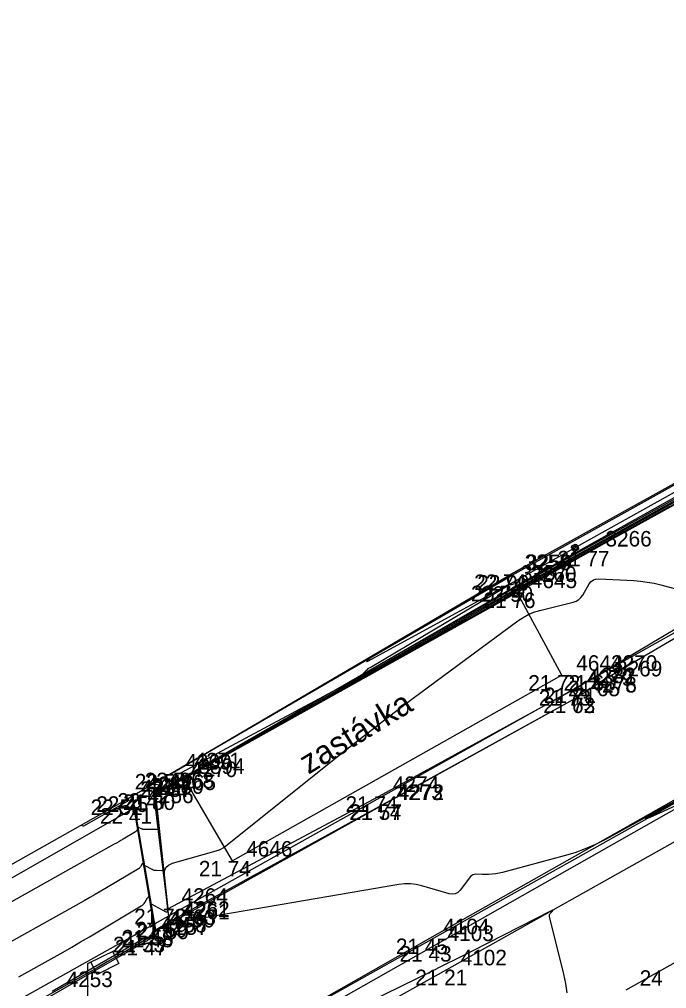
# Model space of a CAD drawing. Extents: x -702257 to -701487, y -1009871 to -1008841.
# Drawn here: x -701987.85 to -701977.44, y -1009621.47 to -1009605.88 of the extents above; entities that cross this region are included whole.
import ezdxf

# ---------------------------------------------------------------- set-up
doc = ezdxf.new("R2010")
doc.units = 0
for name, color, linetype in [('Ex_Major Contours', 7, 'Continuous'), ('Ex_Minor Contours', 7, 'Continuous'), ('Z_betonova_konstrukce', 7, 'Continuous'), ('Z_body', 7, 'Continuous'), ('Z_body_cisla', 7, 'Continuous'), ('Z_body_vysky_redukovane', 7, 'Continuous'), ('Z_katastr_hranice', 7, 'Continuous'), ('Z_komunikace', 7, 'Continuous'), ('Z_obruba', 7, 'Continuous'), ('Z_popisy', 7, 'Continuous'), ('Z_rozhranni', 7, 'Continuous'), ('Z_site_vo_znaky', 7, 'Continuous'), ('Z_zabradli', 7, 'Continuous'), ('Z_zabradli_znaky', 7, 'Continuous')]:
    doc.layers.add(name, color=color, linetype=linetype)

# ---------------------------------------------------------------- blocks, each defined once
blk = doc.blocks.new('POINT_DISPLAY')
blk.add_line((0, 0), (0, 0))
blk = doc.blocks.new('Z13')
for p, q in [((0, 0.88), (0.45, 1.1)), ((0.4, 1.07), (0.5, 0.88)), ((0, 0.2), (0, 0.88)), ((0.15, 0.7), (0.05, 0.9)), ((0.5, 0.88), (0.15, 0.7)), ((-0.15, 0.15), (-0.05, 0.2)), ((-0.05, 0.2), (0.05, 0.2)), ((0.05, 0.2), (0.15, 0.15)), ((-0.2, 0.05), (-0.15, 0.15)), ((-0.2, -0.05), (-0.2, 0.05)), ((0.15, 0.15), (0.2, 0.05)), ((0.2, 0.05), (0.2, -0.05)), ((-0.15, -0.15), (-0.2, -0.05)), ((-0.05, -0.2), (-0.15, -0.15)), ((0.15, -0.15), (0.05, -0.2)), ((0.2, -0.05), (0.15, -0.15)), ((0.05, -0.2), (-0.05, -0.2))]:
    blk.add_line(p, q)
blk = doc.blocks.new('Z530')
for p, q in [((-0.05, 0.03), (-0.03, 0.05)), ((-0.05, -0.03), (-0.05, 0.03)), ((-0.03, 0.05), (0.03, 0.05)), ((-0.03, -0.03), (-0.03, 0.03)), ((-0.03, 0.03), (0.03, 0.03)), ((-0.03, -0.03), (0.03, 0.03)), ((0.03, 0.05), (0.05, 0.03)), ((0.03, 0.03), (0.03, -0.03)), ((0.05, 0.03), (0.05, -0.03)), ((-0.03, -0.05), (-0.05, -0.03)), ((0.03, -0.03), (-0.03, -0.03)), ((0.03, -0.05), (-0.03, -0.05)), ((0.05, -0.03), (0.03, -0.05))]:
    blk.add_line(p, q)

msp = doc.modelspace()

# ---------------------------------------------------------------- linework, layer by layer
at = {"layer": 'Ex_Major Contours'}
msp.add_lwpolyline([(-701977.395, -1009613.72), (-701979.437, -1009614.853), (-701979.64, -1009614.966), (-701979.844, -1009615.08), (-701980.046, -1009615.194), (-701980.249, -1009615.309), (-701981.059, -1009615.77), (-701981.261, -1009615.885), (-701981.464, -1009616), (-701981.667, -1009616.114), (-701981.871, -1009616.228), (-701985.231, -1009618.103), (-701985.231, -1009618.105), (-701985.548, -1009618.282), (-701985.56, -1009618.289), (-701985.572, -1009618.295), (-701985.584, -1009618.301), (-701985.596, -1009618.308), (-701985.645, -1009618.332), (-701985.655, -1009618.339), (-701985.662, -1009618.348), (-701985.666, -1009618.358), (-701985.666, -1009618.371), (-701985.548, -1009619.475), (-701985.546, -1009619.496), (-701985.544, -1009619.516), (-701985.541, -1009619.557), (-701985.542, -1009619.566), (-701985.545, -1009619.572), (-701985.551, -1009619.576), (-701985.56, -1009619.577), (-701985.645, -1009619.576), (-701985.663, -1009619.575), (-701985.68, -1009619.572), (-701985.696, -1009619.567), (-701985.712, -1009619.559), (-701985.828, -1009619.497), (-701985.833, -1009619.496), (-701985.836, -1009619.496), (-701985.838, -1009619.499), (-701985.838, -1009619.504), (-701985.837, -1009619.527), (-701985.837, -1009619.531), (-701985.838, -1009619.533), (-701985.839, -1009619.531), (-701985.84, -1009619.527), (-701985.854, -1009619.47), (-701985.858, -1009619.461), (-701985.862, -1009619.458), (-701985.867, -1009619.46), (-701985.872, -1009619.467), (-701985.899, -1009619.513), (-701985.906, -1009619.523), (-701985.914, -1009619.532), (-701985.924, -1009619.54), (-701985.934, -1009619.547), (-701986.449, -1009619.854), (-701986.538, -1009619.907), (-701986.628, -1009619.959), (-701986.718, -1009620.011), (-701986.809, -1009620.062), (-701988.502, -1009621.008)], dxfattribs=at)
at = {"layer": 'Ex_Minor Contours'}
for points in [[(-701984.982, -1009617.764), (-701985.66, -1009618.165), (-701985.67, -1009618.172), (-701985.672, -1009618.177), (-701985.668, -1009618.181), (-701985.657, -1009618.184), (-701985.589, -1009618.194), (-701985.581, -1009618.197), (-701985.575, -1009618.201), (-701985.572, -1009618.208), (-701985.572, -1009618.216), (-701985.577, -1009618.254), (-701985.577, -1009618.262), (-701985.574, -1009618.266), (-701985.569, -1009618.267), (-701985.562, -1009618.264), (-701985.362, -1009618.164), (-701985.351, -1009618.159), (-701985.34, -1009618.153), (-701985.309, -1009618.136), (-701984.962, -1009617.942), (-701984.904, -1009617.909), (-701984.847, -1009617.877), (-701984.789, -1009617.844), (-701984.731, -1009617.812), (-701981.101, -1009615.746), (-701980.477, -1009615.391), (-701979.851, -1009615.039), (-701979.224, -1009614.688), (-701978.597, -1009614.338), (-701971.729, -1009610.529)], [(-701973.734, -1009611.616), (-701979.232, -1009614.666), (-701979.545, -1009614.84), (-701979.856, -1009615.015), (-701980.168, -1009615.19), (-701980.478, -1009615.367), (-701982.31, -1009616.409), (-701982.322, -1009616.415), (-701982.327, -1009616.416), (-701982.325, -1009616.412), (-701982.316, -1009616.401), (-701982.264, -1009616.349), (-701982.251, -1009616.337), (-701982.237, -1009616.325), (-701982.222, -1009616.315), (-701982.206, -1009616.305), (-701979.994, -1009614.992), (-701979.992, -1009614.99), (-701979.992, -1009614.988), (-701979.994, -1009614.982), (-701979.995, -1009614.98), (-701979.998, -1009614.981), (-701982.251, -1009616.212), (-701982.259, -1009616.215), (-701982.262, -1009616.216), (-701982.261, -1009616.212), (-701982.255, -1009616.206), (-701982.223, -1009616.171), (-701982.215, -1009616.162), (-701982.206, -1009616.155), (-701982.197, -1009616.148), (-701982.187, -1009616.141), (-701980.104, -1009614.903), (-701980.026, -1009614.857), (-701979.947, -1009614.812), (-701979.869, -1009614.767), (-701979.79, -1009614.723), (-701979.316, -1009614.458)], [(-701974.562, -1009612.124), (-701979.017, -1009614.596), (-701979.432, -1009614.827), (-701979.847, -1009615.059), (-701980.262, -1009615.293), (-701980.675, -1009615.528), (-701982.629, -1009616.639), (-701982.892, -1009616.789), (-701983.156, -1009616.938), (-701983.42, -1009617.086), (-701983.684, -1009617.234), (-701985.27, -1009618.119), (-701985.27, -1009618.12), (-701985.413, -1009618.201), (-701985.437, -1009618.214), (-701985.462, -1009618.227), (-701985.486, -1009618.239), (-701985.51, -1009618.252), (-701985.625, -1009618.309), (-701985.649, -1009618.325), (-701985.665, -1009618.345), (-701985.673, -1009618.369), (-701985.674, -1009618.397), (-701985.624, -1009618.866), (-701985.622, -1009618.885), (-701985.62, -1009618.904), (-701985.621, -1009618.908), (-701985.622, -1009618.911), (-701985.625, -1009618.913), (-701985.629, -1009618.914), (-701985.855, -1009618.912), (-701985.865, -1009618.911), (-701985.874, -1009618.909), (-701985.883, -1009618.906), (-701985.892, -1009618.902), (-701985.929, -1009618.883), (-701985.936, -1009618.88), (-701985.941, -1009618.881), (-701985.944, -1009618.885), (-701985.944, -1009618.893), (-701985.943, -1009618.939), (-701985.943, -1009618.942), (-701985.943, -1009618.943), (-701985.944, -1009618.942), (-701985.945, -1009618.939), (-701985.949, -1009618.921), (-701985.951, -1009618.918), (-701985.952, -1009618.917), (-701985.954, -1009618.917), (-701985.956, -1009618.92), (-701985.967, -1009618.938), (-701985.969, -1009618.942), (-701985.973, -1009618.946), (-701985.976, -1009618.949), (-701985.98, -1009618.951), (-701986.181, -1009619.071), (-701986.216, -1009619.092), (-701986.251, -1009619.112), (-701986.286, -1009619.132), (-701986.322, -1009619.152), (-701989.72, -1009621.052)], [(-701987.86, -1009621.286), (-701987.289, -1009620.967), (-701987.147, -1009620.887), (-701987.005, -1009620.806), (-701986.864, -1009620.724), (-701986.723, -1009620.641), (-701985.888, -1009620.143), (-701985.871, -1009620.132), (-701985.856, -1009620.119), (-701985.843, -1009620.104), (-701985.832, -1009620.087), (-701985.788, -1009620.015), (-701985.779, -1009620.003), (-701985.771, -1009619.999), (-701985.765, -1009620.005), (-701985.759, -1009620.019), (-701985.733, -1009620.124), (-701985.732, -1009620.126), (-701985.732, -1009620.115), (-701985.732, -1009620.113), (-701985.731, -1009620.112), (-701985.73, -1009620.111), (-701985.728, -1009620.112), (-701985.493, -1009620.237), (-701985.49, -1009620.239), (-701985.486, -1009620.24), (-701985.483, -1009620.24), (-701985.48, -1009620.241), (-701985.466, -1009620.241), (-701985.463, -1009620.24), (-701985.461, -1009620.239), (-701985.46, -1009620.237), (-701985.46, -1009620.234), (-701985.467, -1009620.147), (-701985.468, -1009620.131), (-701985.469, -1009620.116), (-701985.471, -1009620.1), (-701985.473, -1009620.084), (-701985.519, -1009619.654), (-701985.516, -1009619.584), (-701985.494, -1009619.528), (-701985.45, -1009619.486), (-701985.386, -1009619.458), (-701984.648, -1009619.248), (-701984.637, -1009619.244), (-701984.627, -1009619.24), (-701984.617, -1009619.236), (-701984.608, -1009619.231), (-701984.569, -1009619.209), (-701984.56, -1009619.204), (-701984.55, -1009619.198), (-701984.542, -1009619.191), (-701984.533, -1009619.185), (-701982.73, -1009617.74), (-701982.429, -1009617.502), (-701982.126, -1009617.266), (-701981.82, -1009617.033), (-701981.513, -1009616.803), (-701979.83, -1009615.558), (-701979.743, -1009615.5), (-701979.651, -1009615.451), (-701979.555, -1009615.412), (-701979.454, -1009615.382), (-701978.938, -1009615.255), (-701978.891, -1009615.238), (-701978.85, -1009615.214), (-701978.815, -1009615.182), (-701978.785, -1009615.141), (-701978.68, -1009614.963), (-701978.651, -1009614.925), (-701978.615, -1009614.898), (-701978.573, -1009614.883), (-701978.525, -1009614.88), (-701977.966, -1009614.909), (-701977.856, -1009614.917), (-701977.747, -1009614.932), (-701977.639, -1009614.952), (-701977.532, -1009614.978), (-701976.619, -1009615.225)], [(-701976.771, -1009618.167), (-701978.422, -1009619.073), (-701978.582, -1009619.154), (-701978.746, -1009619.226), (-701978.914, -1009619.288), (-701979.086, -1009619.34), (-701980.074, -1009619.607), (-701980.101, -1009619.614), (-701980.129, -1009619.619), (-701980.157, -1009619.623), (-701980.185, -1009619.626), (-701980.303, -1009619.636), (-701980.329, -1009619.638), (-701980.354, -1009619.639), (-701980.379, -1009619.639), (-701980.405, -1009619.638), (-701980.507, -1009619.634), (-701980.531, -1009619.636), (-701980.553, -1009619.643), (-701980.572, -1009619.655), (-701980.589, -1009619.673), (-701980.759, -1009619.891), (-701980.795, -1009619.927), (-701980.836, -1009619.948), (-701980.882, -1009619.955), (-701980.932, -1009619.947), (-701981.375, -1009619.822), (-701981.467, -1009619.801), (-701981.559, -1009619.791), (-701981.652, -1009619.791), (-701981.746, -1009619.802), (-701985.376, -1009620.419), (-701985.408, -1009620.426), (-701985.438, -1009620.435), (-701985.468, -1009620.447), (-701985.497, -1009620.461), (-701985.66, -1009620.549), (-701985.663, -1009620.551), (-701985.666, -1009620.551), (-701985.669, -1009620.549), (-701985.67, -1009620.545), (-701985.675, -1009620.526), (-701985.676, -1009620.523), (-701985.678, -1009620.522), (-701985.68, -1009620.522), (-701985.682, -1009620.525), (-701985.711, -1009620.573), (-701985.717, -1009620.583), (-701985.723, -1009620.591), (-701985.729, -1009620.6), (-701985.736, -1009620.608), (-701985.769, -1009620.647), (-701985.777, -1009620.655), (-701985.786, -1009620.663), (-701985.796, -1009620.671), (-701985.806, -1009620.677), (-701986.272, -1009620.951), (-701986.353, -1009620.998), (-701986.435, -1009621.045), (-701986.516, -1009621.092), (-701986.598, -1009621.138), (-701987.672, -1009621.743)], [(-701977.175, -1009618.482), (-701977.656, -1009618.697), (-701977.746, -1009618.736), (-701977.779, -1009618.745), (-701977.752, -1009618.725), (-701977.667, -1009618.676), (-701976.769, -1009618.171)], [(-701986.848, -1009618.842), (-701986.826, -1009618.855), (-701986.822, -1009618.857), (-701986.818, -1009618.857), (-701986.815, -1009618.857), (-701986.811, -1009618.855), (-701986.109, -1009618.46), (-701986.105, -1009618.458), (-701986.102, -1009618.454), (-701986.1, -1009618.45), (-701986.099, -1009618.446), (-701986.094, -1009618.416)], [(-701979.037, -1009621.543), (-701979.046, -1009621.467), (-701979.058, -1009621.391), (-701979.073, -1009621.315), (-701979.09, -1009621.241), (-701979.319, -1009620.312), (-701979.32, -1009620.3), (-701979.319, -1009620.288), (-701979.315, -1009620.277), (-701979.308, -1009620.266), (-701979.274, -1009620.226), (-701979.269, -1009620.217), (-701979.268, -1009620.213), (-701979.272, -1009620.213), (-701979.281, -1009620.217), (-701980.578, -1009620.877), (-701980.798, -1009620.989), (-701981.019, -1009621.099), (-701981.24, -1009621.209), (-701981.462, -1009621.318), (-701985.338, -1009623.215)]]:
    msp.add_lwpolyline(points, dxfattribs=at)
at = {"layer": 'Z_betonova_konstrukce'}
for p, q in [((-701969.8, -1009609.18), (-701979.95, -1009614.81)), ((-701979.92, -1009614.82), (-701969.8, -1009609.19)), ((-701969.73, -1009609.32), (-701979.86, -1009615)), ((-701979.84, -1009615.1), (-701969.69, -1009609.38)), ((-701985.41, -1009618.02), (-701979.95, -1009614.81)), ((-701985.41, -1009618.02), (-701979.92, -1009614.82)), ((-701985.66, -1009618.35), (-701979.84, -1009615.1)), ((-701979.86, -1009615), (-701985.32, -1009618.14)), ((-701985.25, -1009618), (-701979.84, -1009615.1)), ((-701979.12, -1009616.43), (-701979.84, -1009615.1)), ((-701979.12, -1009616.43), (-701984.42, -1009619.42)), ((-701982.06, -1009618.38), (-701978.95, -1009616.67)), ((-701978.95, -1009616.67), (-701978.88, -1009616.79)), ((-701982, -1009618.51), (-701978.88, -1009616.79)), ((-701981.99, -1009618.51), (-701978.88, -1009616.79)), ((-701985.41, -1009618.02), (-701986.03, -1009618.38)), ((-701985.2, -1009618.09), (-701985.25, -1009618)), ((-701984.42, -1009619.42), (-701985.2, -1009618.09)), ((-701985.69, -1009618.33), (-701985.32, -1009618.14)), ((-701986.03, -1009618.38), (-701985.66, -1009620.53)), ((-701985.69, -1009618.33), (-701985.44, -1009620.4)), ((-701985.66, -1009618.35), (-701985.46, -1009620.19)), ((-701985.46, -1009620.19), (-701982.06, -1009618.38)), ((-701986.01, -1009618.57), (-701985.67, -1009620.56)), ((-701985.44, -1009620.43), (-701981.99, -1009618.51)), ((-701985.44, -1009620.4), (-701982, -1009618.51)), ((-701985.44, -1009620.43), (-701985.67, -1009620.56)), ((-701985.66, -1009620.53), (-701985.44, -1009620.4))]:
    msp.add_line(p, q, dxfattribs=at)
at = {"layer": 'Z_katastr_hranice'}
for p, q in [((-702014.27, -1009636.43), (-701959.3, -1009605.67)), ((-702013.06, -1009638.53), (-701957.87, -1009607.59))]:
    msp.add_line(p, q, dxfattribs=at)
at = {"layer": 'Z_komunikace'}
for p, q in [((-701966.34, -1009612.97), (-701980.98, -1009621.17)), ((-701980.98, -1009621.17), (-701990.13, -1009626.29))]:
    msp.add_line(p, q, dxfattribs=at)
at = {"layer": 'Z_obruba'}
for p, q in [((-701966.68, -1009612.41), (-701981.25, -1009620.67)), ((-701981.19, -1009620.79), (-701966.6, -1009612.51)), ((-701978.55, -1009616.43), (-701976.84, -1009615.41)), ((-701978.48, -1009616.52), (-701976.77, -1009615.52)), ((-701978.95, -1009616.67), (-701978.55, -1009616.43)), ((-701978.88, -1009616.79), (-701978.48, -1009616.52)), ((-701986.03, -1009618.38), (-701986.12, -1009618.43)), ((-701986.12, -1009618.43), (-701998.5, -1009625.43)), ((-701990.66, -1009621.22), (-701986.01, -1009618.57)), ((-701981.25, -1009620.67), (-701990.38, -1009625.84)), ((-701989.56, -1009622.86), (-701985.77, -1009620.69)), ((-701985.8, -1009620.64), (-701987.32, -1009621.52)), ((-701985.77, -1009620.69), (-701985.8, -1009620.64)), ((-701990.32, -1009625.96), (-701981.19, -1009620.79))]:
    msp.add_line(p, q, dxfattribs=at)
at = {"layer": 'Z_rozhranni'}
for p, q in [((-701966.58, -1009614.98), (-701978.09, -1009621.5)), ((-701985.67, -1009620.56), (-701985.77, -1009620.69))]:
    msp.add_line(p, q, dxfattribs=at)
at = {"layer": 'Z_zabradli'}
for p, q in [((-701980, -1009614.99), (-701968.84, -1009608.74)), ((-701968.72, -1009608.92), (-701978.65, -1009614.43))]:
    msp.add_line(p, q, dxfattribs=at)

# ---------------------------------------------------------------- block references
at = {"layer": 'Z_body'}
for p in [(-701978.65, -1009614.43), (-701979.95, -1009614.81), (-701979.92, -1009614.82), (-701980, -1009614.99), (-701979.86, -1009615), (-701979.84, -1009615.1), (-701979.12, -1009616.43), (-701978.55, -1009616.43), (-701978.48, -1009616.52), (-701978.95, -1009616.67), (-701978.91, -1009616.63), (-701978.88, -1009616.79), (-701978.88, -1009616.79), (-701985.41, -1009618.02), (-701985.25, -1009618), (-701985.2, -1009618.09), (-701985.32, -1009618.14), (-701986.03, -1009618.38), (-701985.69, -1009618.33), (-701985.66, -1009618.35), (-701982.06, -1009618.38), (-701986.12, -1009618.43), (-701986.01, -1009618.57), (-701982, -1009618.51), (-701981.99, -1009618.51), (-701984.42, -1009619.42), (-701985.46, -1009620.19), (-701985.44, -1009620.4), (-701985.44, -1009620.43), (-701985.67, -1009620.56), (-701985.66, -1009620.53), (-701985.8, -1009620.64), (-701985.77, -1009620.69), (-701981.25, -1009620.67), (-701981.19, -1009620.79), (-701980.98, -1009621.17)]:
    msp.add_blockref('POINT_DISPLAY', p, dxfattribs=at)
at = {"layer": 'Z_site_vo_znaky'}
msp.add_blockref('Z13', (-701986.75, -1009621.95), dxfattribs=at)
at = {"layer": 'Z_zabradli_znaky', "rotation": 29.300000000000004}
msp.add_blockref('Z530', (-701978.91, -1009614.38), dxfattribs=at)

# ---------------------------------------------------------------- texts
at = {"layer": 'Z_body_cisla'}
for s, p in [('3266', (-701978.42, -1009614.36)), ('3258', (-701979.72, -1009614.74)), ('3259', (-701979.7, -1009614.74)), ('3257', (-701979.78, -1009614.91)), ('3260', (-701979.63, -1009614.93)), ('4645', (-701979.62, -1009615.03)), ('4644', (-701978.89, -1009616.36)), ('3270', (-701978.33, -1009616.36)), ('3269', (-701978.25, -1009616.45)), ('4279', (-701978.72, -1009616.6)), ('4282', (-701978.68, -1009616.56)), ('4276', (-701978.66, -1009616.71)), ('4278', (-701978.66, -1009616.71)), ('4269', (-701985.18, -1009617.95)), ('4271', (-701985.03, -1009617.93)), ('3894', (-701984.97, -1009618.02)), ('4270', (-701985.09, -1009618.07)), ('4255', (-701985.89, -1009618.36)), ('4267', (-701985.8, -1009618.31)), ('4268', (-701985.46, -1009618.25)), ('4265', (-701985.43, -1009618.28)), ('4274', (-701981.84, -1009618.31)), ('4256', (-701985.79, -1009618.49)), ('4273', (-701981.78, -1009618.44)), ('4272', (-701981.76, -1009618.44)), ('4646', (-701984.2, -1009619.35)), ('4264', (-701985.24, -1009620.11)), ('4262', (-701985.21, -1009620.32)), ('4261', (-701985.21, -1009620.36)), ('4260', (-701985.45, -1009620.49)), ('4263', (-701985.43, -1009620.45)), ('4258', (-701985.58, -1009620.57)), ('4257', (-701985.55, -1009620.61)), ('4104', (-701981.03, -1009620.6)), ('4103', (-701980.96, -1009620.71)), ('4102', (-701980.75, -1009621.1)), ('4253', (-701987.09, -1009621.45)), ('24', (-701977.87, -1009621.43))]:
    msp.add_text(s, height=0.25, dxfattribs=at).set_placement(p)
at = {"layer": 'Z_body_vysky_redukovane'}
for s, p in [('21 77', (-701979.192, -1009614.68)), ('22 74', (-701980.533, -1009615.06)), ('22 90', (-701980.483, -1009615.07)), ('22 74', (-701980.583, -1009615.24)), ('22 90', (-701980.422, -1009615.25)), ('21 76', (-701980.382, -1009615.35)), ('21 72', (-701979.662, -1009616.68)), ('21 68', (-701979.092, -1009616.68)), ('21 65', (-701979.022, -1009616.77)), ('21 73', (-701979.492, -1009616.92)), ('21 71', (-701979.41, -1009616.88)), ('21 73', (-701979.422, -1009617.04)), ('21 62', (-701979.422, -1009617.04)), ('22 54', (-701985.993, -1009618.27)), ('22 56', (-701985.833, -1009618.25)), ('21 80', (-701985.721, -1009618.34)), ('22 57', (-701985.903, -1009618.39)), ('22 52', (-701986.703, -1009618.68)), ('22 45', (-701986.613, -1009618.63)), ('22 47', (-701986.273, -1009618.58)), ('21 80', (-701986.181, -1009618.6)), ('21 74', (-701982.602, -1009618.63)), ('22 41', (-701986.552, -1009618.82)), ('21 74', (-701982.542, -1009618.76)), ('21 57', (-701982.532, -1009618.76)), ('21 74', (-701984.962, -1009619.67)), ('21 72', (-701986.002, -1009620.44)), ('21 69', (-701985.982, -1009620.65)), ('21 50', (-701985.961, -1009620.68)), ('21 48', (-701986.212, -1009620.81)), ('21 58', (-701986.202, -1009620.78)), ('21 53', (-701986.342, -1009620.89)), ('21 47', (-701986.312, -1009620.94)), ('21 45', (-701981.792, -1009620.92)), ('21 43', (-701981.732, -1009621.04)), ('21 21', (-701981.48, -1009621.42))]:
    msp.add_text(s, height=0.25, dxfattribs=at).set_placement(p)
at = {"layer": 'Z_popisy'}
msp.add_text('zastávka', height=0.38, rotation=31.5, dxfattribs=at).set_placement((-701983.198, -1009618.034))

doc.saveas('drawing.dxf')
